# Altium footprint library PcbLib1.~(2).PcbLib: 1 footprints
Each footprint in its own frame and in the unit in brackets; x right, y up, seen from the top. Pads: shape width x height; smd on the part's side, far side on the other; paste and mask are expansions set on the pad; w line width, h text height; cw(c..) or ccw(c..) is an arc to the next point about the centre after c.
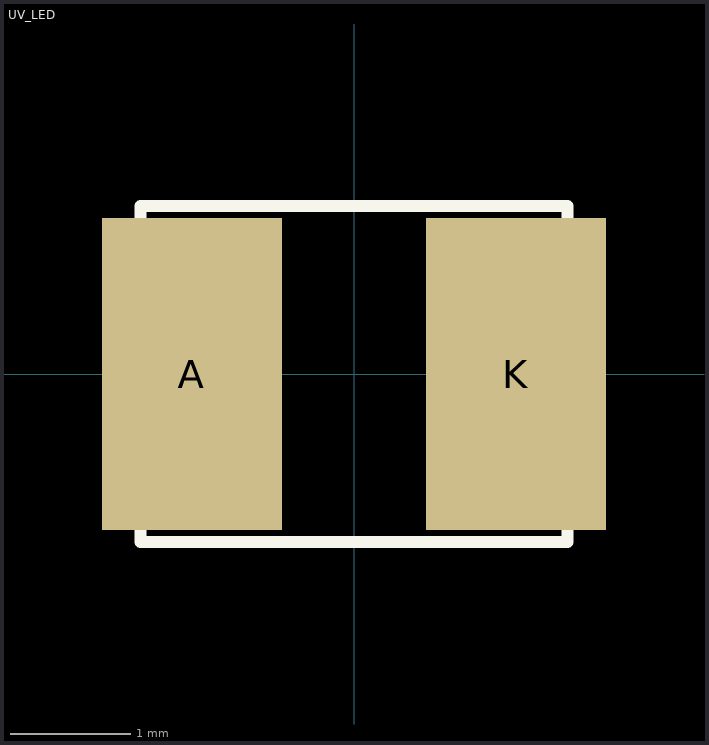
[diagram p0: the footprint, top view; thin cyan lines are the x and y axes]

## UV_LED [mm]
pads (2):
  rect 1.5x2.6 smd: A(-1.35,0) K(1.35,0)
Top Overlay:
  lines w0.1: -1.778,-1.4 1.778,-1.4 1.778,1.4 -1.778,1.4 -1.778,-1.4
